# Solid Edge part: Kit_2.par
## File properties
Author: bmolnar
Last saved by: bmolnar
Revision: 76
Sűrűség: 0,000 kg/m^3
Pontosság: 0,990
Username: bmolnar
Dokumentum tartalom típus: 0
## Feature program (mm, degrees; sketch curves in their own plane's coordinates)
base feature "unnamed BaseFeature 1"
sketch for "Furat_1" plane through (-20.15, 0, 96.65) normal (1, 0, 0) x-axis (0, 1, 0)
  hole centre (0, -15.15) bore radius 2.067
hole "Furat_1" nominal diameter 5 finite  ThreadDepth = 5 mm; StartChamferOffset = 0.6 mm; StartChamferAngle = 45 deg
sketch for "Furat_2" plane through (-13, -13, 83.9) normal (0, 0, 1) x-axis (0, 1, 0)
  hole centre (0, 0) bore radius 2.067
hole "Furat_2" nominal diameter 5
sketch for "unnamed Hole 1" plane through (-13, -13, 83.9) normal (0, 0, 1) x-axis (0, 1, 0)
  hole centre (26, 0) bore radius 2.067
hole "unnamed Hole 1"
sketch for "unnamed Hole 2" plane through (-13, -13, 83.9) normal (0, 0, 1) x-axis (0, 1, 0)
  hole centre (26, -26) bore radius 2.067
hole "unnamed Hole 2"
sketch for "unnamed Hole 3" plane through (-13, -13, 83.9) normal (0, 0, 1) x-axis (0, 1, 0)
  hole centre (0, -26) bore radius 2.067
hole "unnamed Hole 3"
pattern "unnamed Pattern 1" of "Furat_2", "unnamed Hole 1", "unnamed Hole 2", "unnamed Hole 3"
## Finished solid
Body 1: solid body, 265 faces, 630 edges, 376 vertices, 3 internal voids.
  Faces by surface: plane 132, cylinder 56, swept 42, cone 26, torus 9
  Edges by curve: line 381, circle 155, spline 88, curve on surface 5, ellipse 1
Bounding box of the edges (mm; curved faces can reach further): 40.300 x 40.300 x 12.500, from (-20.15, -20.15, 76.5) to (20.15, 20.15, 89).
Cylindrical faces by radius (mm): R0.2 x18, R0.4246 x1, R0.4865 x1, R2.067 x5, R3.75 x2, R4 x4, R4.1 x12, R5.24 x1, R5.45 x2, R5.55 x2, R5.7 x1, R6 x1, R6.92 x1, R7 x1, R13.75 x4
Conical faces (half-angle, radius in mm at the cone's reference point): 0.5 deg R5 x4, 3 deg R6.96 x1, 7 deg R6.4156 x1, 14 deg R5.12 x1, 14 deg R5.3801 x1, 17 deg R5.12 x1, 23 deg R5.7369 x1, 42.5 deg R5.1096 x1, 45 deg R2.317 x2, 45 deg R2.367 x2, 45 deg R2.667 x1, 45 deg R4.25 x2, 45 deg R5.3 x2, 45 deg R5.35 x2, 45 deg R5.85 x1, 84 deg R5.4096 x1, 85 deg R6.73 x1, 87 deg R5.1371 x1
Toroidal faces (ring radius, tube radius in mm): R3.8 r0.2 x2, R4.4 r0.4 x2, R5.6606 r0.18 x1, R6.1131 r0.26 x1, R6.72 r0.2 x1, R9.4957 r0.5 x1, R11.0043 r0.5 x1
Planar faces by outward normal: +x 5, +y 16, +z 17, -x 7, -y 13, -z 5, oblique 69
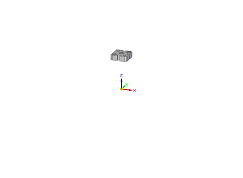
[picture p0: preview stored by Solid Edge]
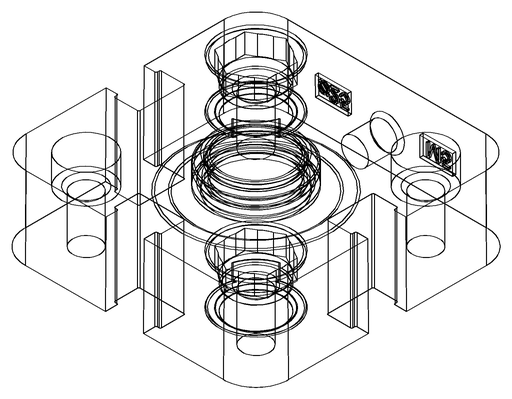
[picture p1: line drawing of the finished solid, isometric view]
